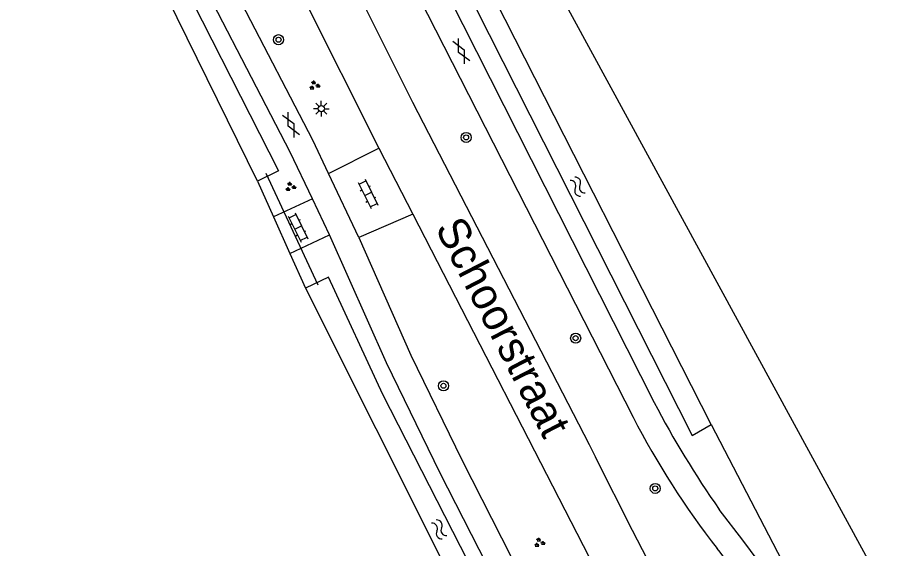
# Model space of a CAD drawing. Extents: x 134297 to 137000, y 403500 to 406000.
# Drawn here: x 135913.4 to 135982.8, y 405075 to 405117.1 of the extents above; entities that cross this region are included whole.
import ezdxf

# ---------------------------------------------------------------- set-up
doc = ezdxf.new("R2010")
doc.units = 0
for name, color, linetype in [('gg-anno-openbare ruimte label', 7, 'Continuous'), ('gg-knt-bronhoudergrens', 7, 'Continuous'), ('gg-knt-verharding', 7, 'Continuous'), ('gg-kntw-bovenkant insteek waterloop', 7, 'Continuous'), ('gg-kwrk-duiker nz buis', 7, 'Continuous'), ('gt-grn-groengrens', 7, 'Continuous'), ('gt-grn-weggrens', 7, 'Continuous'), ('gt-symb-boom', 7, 'Continuous'), ('gt-symb-gesloten verharding', 7, 'Continuous'), ('gt-symb-groenvak', 7, 'Continuous'), ('gt-symb-klinker verharding', 7, 'Continuous'), ('gt-symb-lichtmast', 7, 'Continuous'), ('gt-symb-watersymbool', 7, 'Continuous')]:
    doc.layers.add(name, color=color, linetype=linetype)

# ---------------------------------------------------------------- blocks, each defined once
blk = doc.blocks.new('gt0-BOOM')
at = {"layer": 'gt-symb-boom'}
for radius in [0.4, 0.2]:
    blk.add_circle((0, 0), radius, dxfattribs=at)
blk = doc.blocks.new('gt0-WA')
at = {"layer": 'gt-symb-watersymbool'}
for centre, start, end in [((-0.323, 0.022), 28.07249, 151.92751), ((0.427, 0.422), 208.07248, 331.92751), ((-0.323, -0.428), 28.07249, 151.92751), ((0.427, -0.028), 208.07248, 331.92751)]:
    blk.add_arc(centre, 0.425, start, end, dxfattribs=at)
blk = doc.blocks.new('gt0-GRVAK')
at = {"layer": 'gt-symb-groenvak'}
for p, q in [((-0.11, 0.189), (-0.228, 0.24)), ((-0.182, 0.153), (0.088, 0.153)), ((-0.091, 0.211), (-0.156, 0.322)), ((-0.047, 0.214), (-0.047, 0.393)), ((-0.004, 0.211), (0.061, 0.322)), ((0.015, 0.189), (0.133, 0.24)), ((0.262, -0.052), (0.197, 0.059)), ((0.305, -0.049), (0.305, 0.13)), ((0.349, -0.052), (0.414, 0.059)), ((-0.245, -0.228), (-0.363, -0.177)), ((-0.318, -0.264), (-0.047, -0.264)), ((-0.226, -0.206), (-0.291, -0.095)), ((-0.183, -0.203), (-0.183, -0.024)), ((-0.139, -0.206), (-0.074, -0.095)), ((-0.12, -0.228), (-0.002, -0.177)), ((0.243, -0.074), (0.125, -0.023)), ((0.17, -0.11), (0.441, -0.11)), ((0.368, -0.074), (0.486, -0.023))]:
    blk.add_line(p, q, dxfattribs=at)
blk = doc.blocks.new('gt0-KL1')
at = {"layer": 'gt-symb-klinker verharding'}
for p, q in [((-1.15, 0.3), (1.15, 0.3)), ((-1, -0.3), (-1, 0.3)), ((-0.5, 0.3), (-0.5, 0.45)), ((0, -0.3), (0, 0.3)), ((0.5, 0.3), (0.5, 0.45)), ((1, -0.3), (1, 0.3)), ((-1.15, -0.3), (1.15, -0.3)), ((-0.5, -0.45), (-0.5, -0.3)), ((0.5, -0.45), (0.5, -0.3))]:
    blk.add_line(p, q, dxfattribs=at)
blk = doc.blocks.new('gt0-GESVH1')
at = {"layer": 'gt-symb-gesloten verharding'}
for p, q in [((-0.992, -0.261), (0.008, 0.239)), ((0.008, -0.261), (-0.992, 0.239)), ((0.008, 0.239), (1.008, -0.261)), ((1.008, 0.239), (0.008, -0.261))]:
    blk.add_line(p, q, dxfattribs=at)
blk = doc.blocks.new('gt0-LMAST')
at = {"layer": 'gt-symb-lichtmast'}
for p, q in [((-0.182, 0.173), (-0.447, 0.438)), ((-0.005, 0.246), (-0.005, 0.621)), ((0.172, 0.173), (0.437, 0.438)), ((-0.255, -0.004), (-0.63, -0.004)), ((-0.182, -0.181), (-0.447, -0.446)), ((-0.005, -0.254), (-0.005, -0.629)), ((0.437, -0.446), (0.172, -0.181)), ((0.245, -0.004), (0.62, -0.004))]:
    blk.add_line(p, q, dxfattribs=at)
blk.add_circle((-0.005, -0.004), 0.25, dxfattribs=at)

msp = doc.modelspace()

# ---------------------------------------------------------------- linework, layer by layer
at = {"layer": 'gg-knt-bronhoudergrens'}
msp.add_lwpolyline([(136022.142, 405160.422), (135955.925, 405119.863), (136002.36, 405034.667), (136032.125, 404979.236), (136042.312, 404959.393), (136045.222, 404960.583), (136064.404, 404977.649), (136123.142, 405027.126), (136131.763, 405035.76)], dxfattribs=at)
at = {"layer": 'gg-knt-verharding'}
for p, q in [((135934.991, 405120.791), (135942.039, 405106.716)), ((135944.022, 405121.101), (135962.229, 405085.389)), ((135946.633, 405120.656), (135963.901, 405086.554)), ((135938.051, 405104.718), (135942.039, 405106.716)), ((135942.039, 405106.716), (135944.735, 405101.484)), ((135940.465, 405099.644), (135938.051, 405104.718)), ((135936.771, 405102.715), (135933.666, 405101.286)), ((135938.134, 405099.848), (135936.771, 405102.715)), ((135944.735, 405101.484), (135940.465, 405099.644)), ((135944.735, 405101.484), (135964.91, 405062.327)), ((135934.969, 405098.375), (135938.134, 405099.848))]:
    msp.add_line(p, q, dxfattribs=at)
for points in [[(135936.771, 405102.715), (135935.014, 405106.41), (135925.824, 405124.162), (135920.466, 405134.856), (135915.415, 405145.698)], [(135938.588, 405122.629), (135944.71, 405110.371), (135958.731, 405083.222), (135959.236, 405082.196)], [(135938.051, 405104.718), (135936.799, 405107.351), (135931.172, 405118.207)], [(135959.069, 405057.459), (135957.456, 405060.329), (135946.921, 405080.949), (135942.64, 405089.693), (135938.134, 405099.848)], [(135940.465, 405099.644), (135944.58, 405090.287), (135948.636, 405081.994), (135958.884, 405061.879), (135960.117, 405059.637)], [(135966.954, 405067.178), (135962.175, 405076.393), (135959.236, 405082.196)], [(135972.776, 405073.15), (135970.943, 405075.623), (135969.063, 405078.063)]]:
    msp.add_lwpolyline(points, dxfattribs=at)
for centre, radius, start, end in [((136032.719, 405122.576), 77.675, 207.62959, 214.96441), ((136021.616, 405116.032), 66.827, 207.29338, 217.92234), ((135924.73, 405039.375), 56.721, 32.8134, 38.85673)]:
    msp.add_arc(centre, radius, start, end, dxfattribs=at)
at = {"layer": 'gg-kntw-bovenkant insteek waterloop'}
for p, q in [((135932.403, 405104.107), (135913.351, 405142.833)), ((135968.422, 405084.801), (135951.297, 405118.436)), ((135936.209, 405095.605), (135954.863, 405058.457))]:
    msp.add_line(p, q, dxfattribs=at)
for points in [[(135913.351, 405142.833), (135914.774, 405143.46), (135924.993, 405122.766), (135934.065, 405104.929), (135932.403, 405104.107)], [(135950.123, 405120.741), (135948.653, 405119.987), (135966.925, 405083.935), (135968.422, 405084.801)], [(135954.863, 405058.457), (135956.535, 405059.445), (135942.369, 405087.176), (135938.037, 405096.495), (135936.209, 405095.605)]]:
    msp.add_lwpolyline(points, dxfattribs=at)
at = {"layer": 'gg-kwrk-duiker nz buis'}
msp.add_line((135937.225, 405095.864), (135933.084, 405104.712), dxfattribs=at)
at = {"layer": 'gt-grn-groengrens'}
for p, q in [((135932.403, 405104.107), (135933.666, 405101.286)), ((135934.969, 405098.375), (135936.209, 405095.605)), ((135968.422, 405084.801), (135976.8, 405068.722))]:
    msp.add_line(p, q, dxfattribs=at)
at = {"layer": 'gt-grn-weggrens'}
msp.add_line((135933.666, 405101.286), (135934.969, 405098.375), dxfattribs=at)

# ---------------------------------------------------------------- block references
at = {"layer": 'gt-symb-boom'}
for p in [(135934.078, 405115.328), (135948.974, 405107.576), (135957.67, 405091.649), (135947.175, 405087.868), (135963.993, 405079.729)]:
    msp.add_blockref('gt0-BOOM', p, dxfattribs=at)
at = {"layer": 'gt-symb-gesloten verharding'}
for p, rotation in [((135948.591, 405114.413), 116.30869593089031), ((135935.058, 405108.554), 116.30869593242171)]:
    msp.add_blockref('gt0-GESVH1', p, dxfattribs=dict(at, rotation=rotation))
at = {"layer": 'gt-symb-groenvak'}
for p in [(135936.919, 405111.701), (135935.017, 405103.651), (135954.783, 405075.422)]:
    msp.add_blockref('gt0-GRVAK', p, dxfattribs=at)
at = {"layer": 'gt-symb-klinker verharding', "rotation": -63.69130406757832}
for p in [(135941.186, 405103.092), (135935.63, 405100.425)]:
    msp.add_blockref('gt0-KL1', p, dxfattribs=at)
at = {"layer": 'gt-symb-lichtmast'}
msp.add_blockref('gt0-LMAST', (135937.48, 405109.853), dxfattribs=at)
at = {"layer": 'gt-symb-watersymbool', "rotation": 123.99203971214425}
for p in [(135957.855, 405103.621), (135946.866, 405076.43)]:
    msp.add_blockref('gt0-WA', p, dxfattribs=at)

# ---------------------------------------------------------------- texts
at = {"layer": 'gg-anno-openbare ruimte label'}
msp.add_text('Schoorstraat', height=2.5, rotation=297.3, dxfattribs=at).set_placement((135946.476, 405100.396))

doc.saveas('drawing.dxf')
